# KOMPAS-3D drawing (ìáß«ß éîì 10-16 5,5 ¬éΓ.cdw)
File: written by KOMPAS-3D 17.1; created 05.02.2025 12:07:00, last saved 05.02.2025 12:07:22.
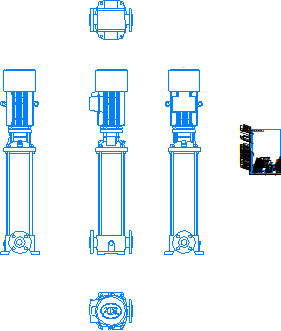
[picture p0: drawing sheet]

Sheet 1: A4, portrait

Title block, sheet 1: name: Насос ВМН 10-16 / 5,5 кВт; designation: Насос ВМН 10-16 5,5 кВт; material: Сталь 10  ГОСТ 1050-2013; mass: 0,08; sheets: 1; sheet format: A4; stored path: \\adlc.lan\data\АДЛ_ПКД\3D-модели\ADL production\Насосы ГРАНПАМП\Насосы ВМН\ВМН10\KOMPAS 3D\Насос ВМН 10-16 5,5 кВт.cdw

Views: Проекционный вид 2, Проекционный вид 3, Проекционный вид 4, Проекционный вид 5
Referenced files in \\adlc.lan\data\АДЛ_ПКД\3D-модели\ADL production\Насосы ГРАНПАМП\Насосы ВМН\ВМН10\KOMPAS 3D\: Насос ВМН 10-16 5,5 кВт.m3d
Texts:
  Andrey
  АДЛ
Dimensions and other numbers on the sheet: 1:1; 1; 5,5 кВт; 0,08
